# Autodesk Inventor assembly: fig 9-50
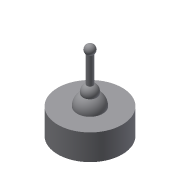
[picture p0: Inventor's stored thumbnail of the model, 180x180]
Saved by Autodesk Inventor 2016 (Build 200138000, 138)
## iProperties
Created: 2013-07
Part Number: fig 9-50
Document SubType Name: Assembly
Designer: CADCIM
Author: CADCIM
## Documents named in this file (3)
- D:\KAVITA\Autodesk Inventor_ 2016 Project_Kavita\Inventor_Part Files\Inventor_2016_Part\c09_Inv_2016\c09_inv_2016_prt\fig 9-50.iam
- D:\KAVITA\Autodesk Inventor_ 2016 Project_Kavita\Inventor_Part Files\Inventor_2016_Part\c09_Inv_2016\c09_inv_2016_prt\19.ipt
- D:\KAVITA\Autodesk Inventor_ 2016 Project_Kavita\Inventor_Part Files\Inventor_2016_Part\c09_Inv_2016\c09_inv_2016_prt\20.ipt
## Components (2 placed, 2 different names)
1. 19:1 — Ball:1
2. 20:1 — Ball:1
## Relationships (1: BallJoint 1)
- Ball:1: 19:1 ↔ 20:1
